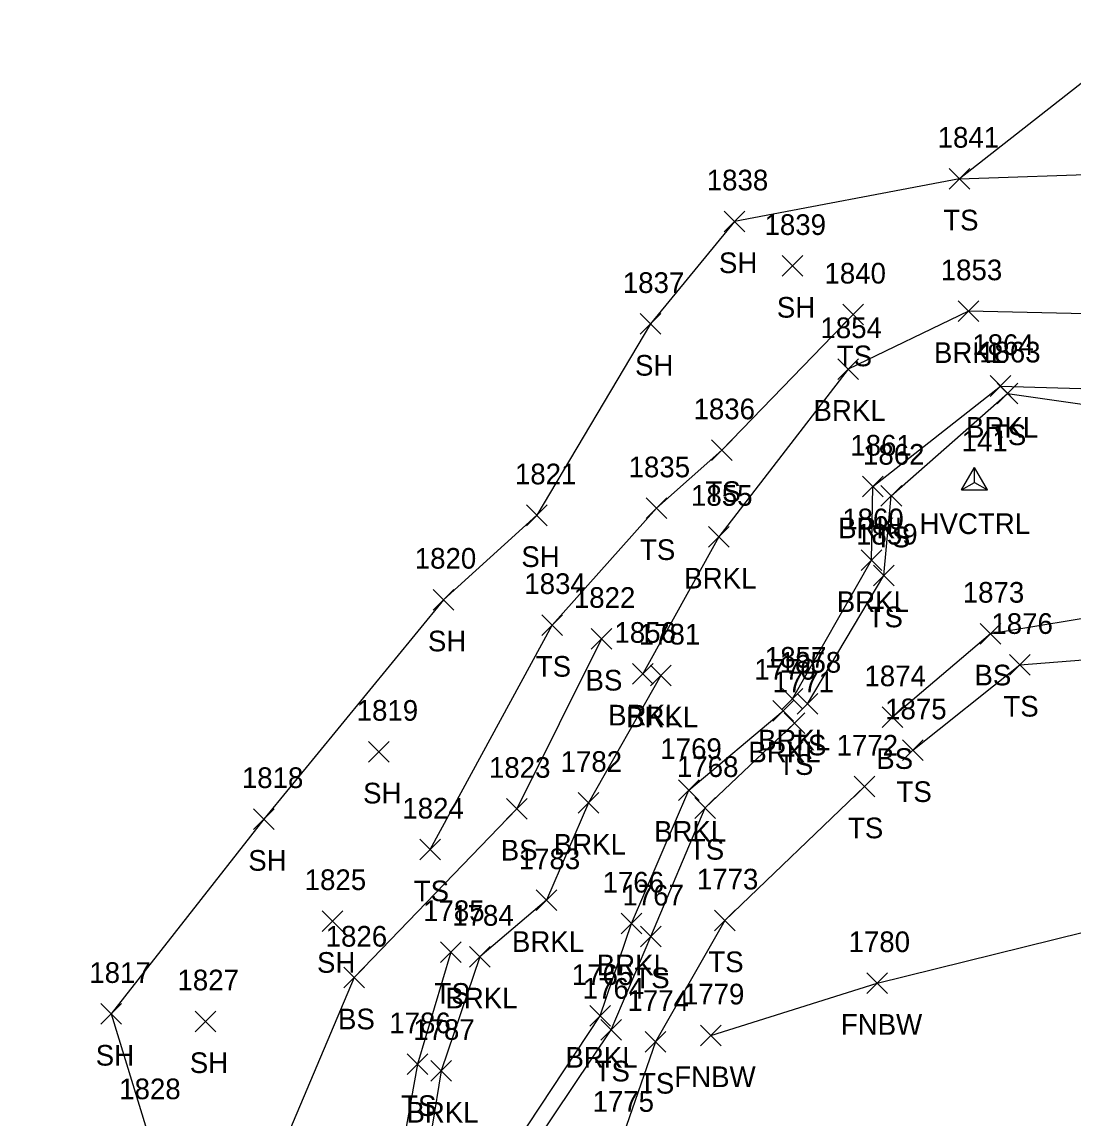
# Model space of a CAD drawing. Extents: x 1526508 to 1531550, y 369926 to 373082.
# Drawn here: x 1531067.4 to 1531169.1, y 370220.6 to 370326.7 of the extents above; entities that cross this region are included whole.
import ezdxf

# ---------------------------------------------------------------- set-up
doc = ezdxf.new("R2010")
doc.units = 0
for name, color, linetype in [('C_A', 7, 'Continuous'), ('C_I', 7, 'Continuous'), ('CPSM', 7, 'Continuous'), ('L_A', 7, 'Continuous'), ('L_I', 7, 'Continuous'), ('L_TIC', 7, 'Continuous'), ('LAWE', 7, 'Continuous'), ('LELB', 7, 'Continuous'), ('LFNC', 7, 'Continuous'), ('LSOGP', 7, 'Continuous')]:
    doc.layers.add(name, color=color, linetype=linetype)

msp = doc.modelspace()

# ---------------------------------------------------------------- linework, layer by layer
at = {"layer": 'CPSM'}
for p, q in [((1531158.34, 370281.41), (1531159.59, 370283.58)), ((1531160.84, 370281.41), (1531159.59, 370283.58)), ((1531159.59, 370282.13), (1531159.59, 370283.58)), ((1531158.34, 370281.41), (1531159.59, 370282.13)), ((1531158.34, 370281.41), (1531160.84, 370281.41)), ((1531159.59, 370282.13), (1531159.59, 370282.13)), ((1531159.59, 370282.13), (1531160.84, 370281.41))]:
    msp.add_line(p, q, dxfattribs=at)
at = {"layer": 'L_TIC'}
for points in [[(1531157.16, 370310.5), (1531159.16, 370312.5)], [(1531159.16, 370310.5), (1531157.16, 370312.5)], [(1531135.38, 370306.37), (1531137.38, 370308.37)], [(1531137.38, 370306.37), (1531135.38, 370308.37)], [(1531140.98, 370302.06), (1531142.98, 370304.06)], [(1531142.98, 370302.06), (1531140.98, 370304.06)], [(1531146.86, 370297.36), (1531148.86, 370299.36)], [(1531148.86, 370297.36), (1531146.86, 370299.36)], [(1531158.02, 370297.68), (1531160.02, 370299.68)], [(1531160.02, 370297.68), (1531158.02, 370299.68)], [(1531127.26, 370296.45), (1531129.26, 370298.45)], [(1531129.26, 370296.45), (1531127.26, 370298.45)], [(1531146.38, 370292.08), (1531148.38, 370294.08)], [(1531148.38, 370292.08), (1531146.38, 370294.08)], [(1531161.12, 370290.45), (1531163.12, 370292.45)], [(1531163.12, 370290.45), (1531161.12, 370292.45)], [(1531161.78, 370289.73), (1531163.78, 370291.73)], [(1531163.78, 370289.73), (1531161.78, 370291.73)], [(1531134.16, 370284.23), (1531136.16, 370286.23)], [(1531136.16, 370284.23), (1531134.16, 370286.23)], [(1531148.75, 370280.72), (1531150.75, 370282.72)], [(1531150.75, 370280.72), (1531148.75, 370282.72)], [(1531150.55, 370279.84), (1531152.55, 370281.84)], [(1531152.55, 370279.84), (1531150.55, 370281.84)], [(1531127.82, 370278.62), (1531129.82, 370280.62)], [(1531129.82, 370278.62), (1531127.82, 370280.62)], [(1531116.26, 370277.94), (1531118.26, 370279.94)], [(1531118.26, 370277.94), (1531116.26, 370279.94)], [(1531133.87, 370275.86), (1531135.87, 370277.86)], [(1531135.87, 370275.86), (1531133.87, 370277.86)], [(1531148.62, 370273.59), (1531150.62, 370275.59)], [(1531150.62, 370273.59), (1531148.62, 370275.59)], [(1531149.84, 370272.11), (1531151.84, 370274.11)], [(1531151.84, 370272.11), (1531149.84, 370274.11)], [(1531107.22, 370269.78), (1531109.22, 370271.78)], [(1531109.22, 370269.78), (1531107.22, 370271.78)], [(1531117.74, 370267.33), (1531119.74, 370269.33)], [(1531119.74, 370267.33), (1531117.74, 370269.33)], [(1531122.52, 370265.99), (1531124.52, 370267.99)], [(1531124.52, 370265.99), (1531122.52, 370267.99)], [(1531160.15, 370266.49), (1531162.15, 370268.49)], [(1531162.15, 370266.49), (1531160.15, 370268.49)], [(1531162.98, 370263.47), (1531164.98, 370265.47)], [(1531164.98, 370263.47), (1531162.98, 370265.47)], [(1531126.51, 370262.61), (1531128.51, 370264.61)], [(1531128.51, 370262.61), (1531126.51, 370264.61)], [(1531128.24, 370262.44), (1531130.24, 370264.44)], [(1531130.24, 370262.44), (1531128.24, 370264.44)], [(1531141, 370260.2), (1531143, 370262.2)], [(1531143, 370260.2), (1531141, 370262.2)], [(1531142.44, 370259.72), (1531144.44, 370261.72)], [(1531144.44, 370259.72), (1531142.44, 370261.72)], [(1531140.07, 370259.04), (1531142.07, 370261.04)], [(1531142.07, 370259.04), (1531140.07, 370261.04)], [(1531150.65, 370258.41), (1531152.65, 370260.41)], [(1531152.65, 370258.41), (1531150.65, 370260.41)], [(1531141.18, 370257.83), (1531143.18, 370259.83)], [(1531143.18, 370257.83), (1531141.18, 370259.83)], [(1531100.95, 370255.07), (1531102.95, 370257.07)], [(1531102.95, 370255.07), (1531100.95, 370257.07)], [(1531152.64, 370255.21), (1531154.64, 370257.21)], [(1531154.64, 370255.21), (1531152.64, 370257.21)], [(1531147.94, 370251.7), (1531149.94, 370253.7)], [(1531149.94, 370251.7), (1531147.94, 370253.7)], [(1531130.95, 370251.37), (1531132.95, 370253.37)], [(1531132.95, 370251.37), (1531130.95, 370253.37)], [(1531121.24, 370250.12), (1531123.24, 370252.12)], [(1531123.24, 370250.12), (1531121.24, 370252.12)], [(1531132.55, 370249.63), (1531134.55, 370251.63)], [(1531134.55, 370249.63), (1531132.55, 370251.63)], [(1531089.84, 370248.56), (1531091.84, 370250.56)], [(1531091.84, 370248.56), (1531089.84, 370250.56)], [(1531114.32, 370249.55), (1531116.32, 370251.55)], [(1531116.32, 370249.55), (1531114.32, 370251.55)], [(1531105.93, 370245.61), (1531107.93, 370247.61)], [(1531107.93, 370245.61), (1531105.93, 370247.61)], [(1531117.19, 370240.71), (1531119.19, 370242.71)], [(1531119.19, 370240.71), (1531117.19, 370242.71)], [(1531096.49, 370238.69), (1531098.49, 370240.69)], [(1531098.49, 370238.69), (1531096.49, 370240.69)], [(1531125.41, 370238.45), (1531127.41, 370240.45)], [(1531127.41, 370238.45), (1531125.41, 370240.45)], [(1531134.43, 370238.75), (1531136.43, 370240.75)], [(1531136.43, 370238.75), (1531134.43, 370240.75)], [(1531127.27, 370237.2), (1531129.27, 370239.2)], [(1531129.27, 370237.2), (1531127.27, 370239.2)], [(1531107.94, 370235.69), (1531109.94, 370237.69)], [(1531109.94, 370235.69), (1531107.94, 370237.69)], [(1531110.75, 370235.24), (1531112.75, 370237.24)], [(1531112.75, 370235.24), (1531110.75, 370237.24)], [(1531098.57, 370233.22), (1531100.57, 370235.22)], [(1531100.57, 370233.22), (1531098.57, 370235.22)], [(1531149.19, 370232.69), (1531151.19, 370234.69)], [(1531151.19, 370232.69), (1531149.19, 370234.69)], [(1531075.08, 370229.71), (1531077.08, 370231.71)], [(1531077.08, 370229.71), (1531075.08, 370231.71)], [(1531122.37, 370229.51), (1531124.37, 370231.51)], [(1531124.37, 370229.51), (1531122.37, 370231.51)], [(1531084.18, 370228.99), (1531086.18, 370230.99)], [(1531086.18, 370228.99), (1531084.18, 370230.99)], [(1531123.43, 370228.18), (1531125.43, 370230.18)], [(1531125.43, 370228.18), (1531123.43, 370230.18)], [(1531133.08, 370227.63), (1531135.08, 370229.63)], [(1531135.08, 370227.63), (1531133.08, 370229.63)], [(1531127.72, 370227), (1531129.72, 370229)], [(1531129.72, 370227), (1531127.72, 370229)], [(1531104.71, 370224.84), (1531106.71, 370226.84)], [(1531106.71, 370224.84), (1531104.71, 370226.84)], [(1531106.99, 370224.2), (1531108.99, 370226.2)], [(1531108.99, 370224.2), (1531106.99, 370226.2)]]:
    msp.add_lwpolyline(points, dxfattribs=at)
at = {"layer": 'LAWE'}
for points in [[(1531194.98, 370297.36), (1531183.62, 370296.04), (1531174.61, 370298.33), (1531159.02, 370298.68), (1531147.38, 370293.08), (1531134.87, 370276.86), (1531127.51, 370263.61)], [(1531142, 370261.2), (1531149.62, 370274.59), (1531149.75, 370281.72), (1531162.12, 370291.45), (1531176.55, 370291.03), (1531194.2, 370291.38)], [(1531129.24, 370263.44), (1531122.24, 370251.12), (1531118.19, 370241.71), (1531111.75, 370236.24), (1531107.99, 370225.2), (1531106.25, 370214.5), (1531102.04, 370209.52), (1531096.56, 370198.93), (1531090.16, 370198.32), (1531085.9, 370192), (1531084.1, 370185.89)], [(1531087.74, 370184.15), (1531095.69, 370190.28), (1531100.63, 370197.83), (1531111.77, 370212.96), (1531123.37, 370230.51), (1531126.41, 370239.45), (1531131.95, 370252.37), (1531141.07, 370260.04)]]:
    msp.add_lwpolyline(points, dxfattribs=at)
at = {"layer": 'LELB'}
for points in [[(1531158.16, 370311.5), (1531173.21, 370312.02), (1531185.85, 370316.16)], [(1531106.93, 370246.61), (1531118.74, 370268.33), (1531128.82, 370279.62), (1531135.16, 370285.23), (1531147.86, 370298.36)], [(1531143.44, 370260.72), (1531150.84, 370273.11), (1531151.55, 370280.84), (1531162.78, 370290.73), (1531175.43, 370288.93), (1531193.79, 370290.24)], [(1531205.34, 370270.42), (1531189.11, 370270.19), (1531173.62, 370269.53), (1531161.15, 370267.49), (1531151.65, 370259.41)], [(1531123.52, 370266.99), (1531115.32, 370250.55), (1531099.57, 370234.22), (1531091.4, 370214.84), (1531087.65, 370204.33)], [(1531153.64, 370256.21), (1531163.98, 370264.47), (1531183.17, 370265.99), (1531196.59, 370263.98), (1531208.01, 370263.57)], [(1531095.84, 370188.64), (1531102.26, 370197.13), (1531113.41, 370212.72), (1531124.43, 370229.18), (1531128.27, 370238.2), (1531133.55, 370250.63), (1531142.18, 370258.83)], [(1531148.94, 370252.7), (1531135.43, 370239.75), (1531128.72, 370228), (1531125.33, 370218.24), (1531119.74, 370210.03)], [(1531108.94, 370236.69), (1531105.71, 370225.84), (1531103.77, 370215.11), (1531100.34, 370210.6), (1531096.22, 370200.26), (1531092.06, 370200.41)]]:
    msp.add_lwpolyline(points, dxfattribs=at)
at = {"layer": 'LFNC'}
msp.add_lwpolyline([(1531134.08, 370228.63), (1531150.19, 370233.69), (1531175.89, 370240.05), (1531199.88, 370245.87), (1531222.28, 370250.96), (1531238.05, 370255.18), (1531253.57, 370259.14), (1531283.27, 370267), (1531318.04, 370276.03), (1531340.6, 370281.65), (1531362.15, 370285.77), (1531399.51, 370294.39), (1531422.47, 370298.84)], dxfattribs=at)
at = {"layer": 'LSOGP'}
msp.add_lwpolyline([(1531177.54, 370326.67), (1531158.16, 370311.5), (1531136.38, 370307.37), (1531128.26, 370297.45), (1531117.26, 370278.94), (1531108.22, 370270.78), (1531090.84, 370249.56), (1531076.08, 370230.71), (1531079.53, 370219.46), (1531075.62, 370215.22), (1531071.94, 370202.31), (1531045.19, 370185.67), (1531041.08, 370185.67), (1531037.14, 370186.29), (1531030.53, 370189.52), (1531026.78, 370191.04), (1531014.55, 370193.66), (1531012.24, 370193.81), (1531009.22, 370193.47), (1530986.53, 370183.09), (1530962.18, 370174.64)], dxfattribs=at)

# ---------------------------------------------------------------- texts
at = {"layer": 'C_A'}
msp.add_text('HVCTRL', height=2, dxfattribs=at).set_placement((1531154.28, 370277.13))
at = {"layer": 'C_I'}
msp.add_text('141', height=2, dxfattribs=at).set_placement((1531158.36, 370285.13))
at = {"layer": 'L_A'}
for s, p in [('TS', (1531156.57, 370306.5)), ('SH', (1531134.87, 370302.37)), ('SH', (1531140.47, 370298.06)), ('TS', (1531146.27, 370293.36)), ('BRKL', (1531155.67, 370293.68)), ('SH', (1531126.75, 370292.45)), ('BRKL', (1531144.02, 370288.08)), ('BRKL', (1531158.77, 370286.45)), ('TS', (1531161.19, 370285.73)), ('TS', (1531133.57, 370280.23)), ('BRKL', (1531146.4, 370276.72)), ('TS', (1531149.96, 370275.84)), ('SH', (1531115.75, 370273.94)), ('TS', (1531127.23, 370274.62)), ('BRKL', (1531131.51, 370271.86)), ('BRKL', (1531146.27, 370269.59)), ('TS', (1531149.25, 370268.11)), ('SH', (1531106.71, 370265.78)), ('TS', (1531117.15, 370263.33)), ('BS', (1531159.59, 370262.49)), ('BS', (1531121.96, 370261.99)), ('TS', (1531162.39, 370259.47)), ('BRKL', (1531124.15, 370258.61)), ('BRKL', (1531125.88, 370258.44)), ('BRKL', (1531138.65, 370256.2)), ('BRKL', (1531137.71, 370255.04)), ('TS', (1531141.85, 370255.72)), ('TS', (1531140.59, 370253.83)), ('BS', (1531150.09, 370254.41)), ('SH', (1531100.44, 370251.07)), ('TS', (1531152.05, 370251.21)), ('TS', (1531147.35, 370247.7)), ('BRKL', (1531128.59, 370247.37)), ('BS', (1531113.76, 370245.55)), ('BRKL', (1531118.89, 370246.12)), ('TS', (1531131.96, 370245.63)), ('SH', (1531089.33, 370244.56)), ('TS', (1531105.34, 370241.61)), ('BRKL', (1531114.84, 370236.71)), ('TS', (1531133.84, 370234.75)), ('SH', (1531095.98, 370234.69)), ('BRKL', (1531123.05, 370234.45)), ('TS', (1531126.68, 370233.2)), ('TS', (1531107.35, 370231.69)), ('BRKL', (1531108.4, 370231.24)), ('BS', (1531098.01, 370229.22)), ('FNBW', (1531146.66, 370228.69)), ('SH', (1531074.57, 370225.71)), ('BRKL', (1531120.02, 370225.51)), ('SH', (1531083.67, 370224.99)), ('TS', (1531122.84, 370224.18)), ('FNBW', (1531130.55, 370223.63)), ('TS', (1531127.13, 370223)), ('TS', (1531104.12, 370220.84)), ('BRKL', (1531104.63, 370220.2))]:
    msp.add_text(s, height=2, dxfattribs=at).set_placement(p)
at = {"layer": 'L_I'}
for s, p in [('1841', (1531156.03, 370314.5)), ('1838', (1531133.69, 370310.37)), ('1839', (1531139.28, 370306.06)), ('1853', (1531156.33, 370301.68)), ('1837', (1531125.57, 370300.45)), ('1840', (1531145.08, 370301.36)), ('1854', (1531144.69, 370296.08)), ('1864', (1531159.38, 370294.45)), ('1863', (1531160.04, 370293.73)), ('1836', (1531132.41, 370288.23)), ('1861', (1531147.58, 370284.72)), ('1862', (1531148.81, 370283.84)), ('1835', (1531126.13, 370282.62)), ('1821', (1531115.13, 370281.94)), ('1855', (1531132.17, 370279.86)), ('1860', (1531146.8, 370277.59)), ('1859', (1531148.14, 370276.11)), ('1820', (1531105.44, 370273.78)), ('1834', (1531116.04, 370271.33)), ('1822', (1531120.83, 370269.99)), ('1873', (1531158.46, 370270.49)), ('1856', (1531124.76, 370266.61)), ('1876', (1531161.23, 370267.47)), ('1781', (1531127.11, 370266.44)), ('1857', (1531139.31, 370264.2)), ('1858', (1531140.75, 370263.72)), ('1770', (1531138.29, 370263.04)), ('1874', (1531148.95, 370262.41)), ('1771', (1531140.06, 370261.83)), ('1875', (1531150.95, 370259.21)), ('1819', (1531099.82, 370259.07)), ('1769', (1531129.2, 370255.37)), ('1772', (1531146.25, 370255.7)), ('1782', (1531119.55, 370254.12)), ('1823', (1531112.62, 370253.55)), ('1768', (1531130.81, 370253.63)), ('1818', (1531088.71, 370252.56)), ('1824', (1531104.24, 370249.61)), ('1783', (1531115.5, 370244.71)), ('1825', (1531094.79, 370242.69)), ('1766', (1531123.61, 370242.45)), ('1773', (1531132.73, 370242.75)), ('1767', (1531125.53, 370241.2)), ('1785', (1531106.25, 370239.69)), ('1784', (1531109.06, 370239.24)), ('1826', (1531096.82, 370237.22)), ('1780', (1531147.41, 370236.69)), ('1817', (1531073.95, 370233.71)), ('1827', (1531082.48, 370232.99)), ('1765', (1531120.63, 370233.51)), ('1764', (1531121.69, 370232.18)), ('1779', (1531131.38, 370231.63)), ('1774', (1531126.02, 370231)), ('1786', (1531102.97, 370228.84)), ('1787', (1531105.29, 370228.2)), ('1828', (1531076.84, 370222.46)), ('1775', (1531122.64, 370221.24))]:
    msp.add_text(s, height=2, dxfattribs=at).set_placement(p)

doc.saveas('drawing.dxf')
